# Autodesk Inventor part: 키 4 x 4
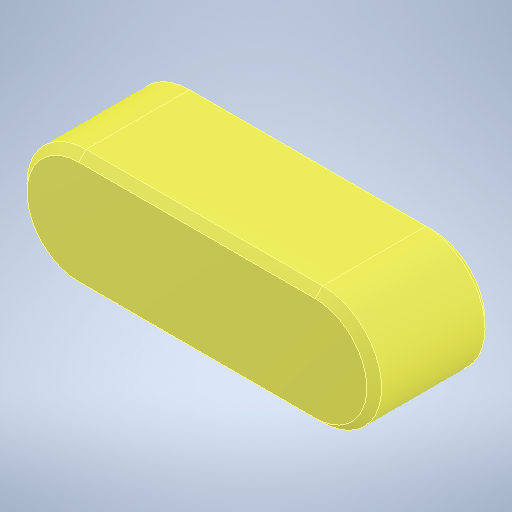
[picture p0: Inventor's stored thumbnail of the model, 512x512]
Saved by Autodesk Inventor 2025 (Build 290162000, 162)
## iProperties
Created: 2024-08
Part Number: 키 4 x 4
Material: 강철, 연강
Description: 키 및 해당 키홈
Document SubType Name: Modeling
Designer: 학생
Density: 7.86 g/cm^3
Appearance: 기본값
Author: jhkim
Sending System: Autodesk Inventor 2025
Preprocessor: ST-DEVELOPER v20
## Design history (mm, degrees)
feature "Solid1"
node "솔리드1"
